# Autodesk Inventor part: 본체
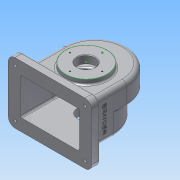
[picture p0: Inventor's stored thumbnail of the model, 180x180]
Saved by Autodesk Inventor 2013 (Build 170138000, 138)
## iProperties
Created: 2017-11
Part Number: 본체
Material: 알루미늄 6061
Document SubType Name: Modeling
Designer: Administrator
Density: 2.71 g/cm^3
Mass: 1079.49 g
Surface Area: 1182.07 cm^2
Volume: 398.334 cm^3
Author: Administrator
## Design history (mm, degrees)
sketch "스케치2"
  geometry: L1 (-75, -50)-(75, -50); L2 (75, -50)-(75, -65); L3 (75, -65)-(-75, -65); L4 (-75, -65)-(-75, -50); L5 (-58, 15)-(-58, -50); L6 (58, 15)-(58, -50); A1 r 58 centre (0, 15) between (58, 15) and (-58, 15); 2 further points
  constraints: 12 end point, 3 perpendicular, 2 parallel, 2 point on circle, 2 point on line, 2 tangent, 2 vertical alignment, 1 centre point, 1 horizontal, 1 midpoint
  dimensions: "d6" = 116 diameter of A1; "d7" = 150 distance of L2.end L3.end; "d8" = 15 distance of L3.end L1.start; "d9" = 65 distance from line of point (0, 0) L3; "d10" = 80 distance from line of A1.centre L3
extrude "돌출2" new body sketch "스케치2" stored distance "d11" = 110; taper "d12" = 0 deg
extrude "돌출3" join sketch "스케치2" distance "d13" = 38; taper "d14" = 0 deg
sketch "스케치3"
  geometry: L1 (58, 15)-(58, -50) reference; L2 (-58, -50)-(-58, 15) reference; L3 (58, -50)-(-58, -50) reference; L4 (-58, -8)-(-58, -50); L5 (58, -8)-(58, -50); L6 (-75, -65)-(75, -65) reference; A1 r 58 centre (0, -8) between (58, -8) and (-58, -8); A2 r 52.126 centre (0, -8) between (-30.872, -50) and (30.872, -50)
  constraints: 4 end point, 4 point on circle, 4 point on line, 2 centre point, 2 collinear
  dimensions: "d18" = 58 radius of A1; "d91" = 57 distance from line of L6 A1.centre
extrude "돌출4" join sketch "스케치3" distance "d19" = 38; taper "d20" = 0 deg
feature "쉘1" dims "d22" = 1000, "d23" = 5
fillet "모깎기2" dims "d24" = 12
node "작업 평면4"
  node "작업 평면3"
sketch "스케치4"
  geometry: L1 (58, 38)-(-58, 38) reference; C1 r 6 at (0, 19); 1 further point
  constraints: 1 centre point, 1 vertical alignment
  dimensions: "d27" = 12 diameter of C1; "d29" = 19 distance from line of C1.centre L1
extrude "돌출5" join sketch "스케치4" stored distance "d30" = 10; taper "d31" = 0 deg
sketch "스케치5"
  geometry: C1 r 6 at (0, 0) reference; 1 further point
hole "구멍1" sketch "스케치5" at (0, 0) diameter "d32" = 4.459; stored, may be unused: countersink angle "d36" = 90 deg, drill point angle "d38" = 0 deg; dims "d33" = 6, "d34" = 4, "d35" = 2, "d37" = 8
sketch "스케치7"
  geometry: C1 r 37.5 at (0, 0); 1 further point
  constraints: 1 centre point, 1 coincident
  dimensions: "d42" = 75 diameter of C1
extrude "돌출7" join sketch "스케치7" distance "d43" = 9; taper "d44" = 0 deg
sketch "스케치11"
  geometry: L1 (0, 0)-(0, 29); C1 r 37.5 at (0, 0) reference
  constraints: 2 end point, 1 vertical
  dimensions: "d62" = 29 distance of L1.start L1.end
hole "구멍3" sketch "스케치11" at (0, 29) diameter "d63" = 2.459; stored, may be unused: countersink angle "d67" = 90 deg, drill point angle "d69" = 118 deg; dims "d64" = 6, "d65" = 4, "d66" = 2, "d68" = 8
sketch "스케치12"
  geometry: A1 r 12 centre (126, 12) between (126, 0) and (138, 12) reference; 1 further point
hole "구멍4" sketch "스케치12" at (126, 12) diameter "d73" = 5; stored, may be unused: countersink angle "d77" = 90 deg, drill point angle "d79" = 0 deg; dims "d74" = 6, "d75" = 12, "d76" = 5, "d78" = 8
fillet "모깎기3" dims "d80" = 3
fillet "모깎기4" dims "d81" = 8
fillet "모깎기6" dims "d83" = 3
fillet "모깎기7" dims "d87" = 3
sketch "스케치13"
  geometry: L1 (46, -57)-(-40, -57) reference; L2 (-35, 23)-(-35, -39) reference; 2 further points
  constraints: 1 other
  dimensions: "d88" = 40 distance from line of point (3, -17) L1; "d119" = 38 distance from line of point (3, -17) L2
feature "엠보싱1" sketch "스케치13" dims "d18" = 58, "d89" = 0.5, "d90" = 0, "d91" = 57
sketch "스케치14"
  geometry: C1 r 1.23 at (0, 29) reference; C2 r 37.5 at (0, 0) reference
sketch "스케치15"
  geometry: C1 r 37.5 at (0, 0) reference; C2 r 16 at (0, 0)
  constraints: 1 centre point, 1 coincident
  dimensions: "d92" = 32 diameter of C2
extrude "돌출10" cut sketch "스케치15" stored distance "d93" = 10; taper "d94" = 0 deg
sketch "스케치16"
  geometry: C1 r 31 at (0, 0); 1 further point
  constraints: 1 centre point, 1 coincident
  dimensions: "d95" = 62 diameter of C1
extrude "돌출11" join sketch "스케치16" distance "d96" = 10; taper "d97" = 0 deg
sketch "스케치17"
  geometry: C1 r 31 at (0, 0) reference; C2 r 16 at (0, 0)
  constraints: 1 centre point, 1 coincident
  dimensions: "d98" = 32 diameter of C2
extrude "돌출12" cut sketch "스케치17" stored distance "d99" = 10; taper "d100" = 0 deg
chamfer "모따기2" distance "d101" = 1; stored, may be unused: second distance "d102" = 2, angle "d103" = 45 deg
sketch "스케치18"
  geometry: L1 (0, 0)-(0, 26); C1 r 17 at (0, 0) reference
  constraints: 2 end point, 1 vertical
  dimensions: "d107" = 26 distance of L1.start L1.end
hole "구멍5" sketch "스케치18" at (0, 26) diameter "d108" = 2.459; stored, may be unused: countersink angle "d112" = 90 deg, drill point angle "d114" = 118 deg; dims "d109" = 6, "d110" = 12, "d111" = 5, "d113" = 8
fillet "모깎기8" dims "d118" = 3
node "솔리드2"
mirror "대칭1"
mirror "대칭2"
pattern_circular "원형 패턴3" dims angle "d105" = 360 deg
pattern_circular "원형 패턴4" dims angle "d116" = 360 deg
other parameters: "d17" = 116, "d26" = 6
